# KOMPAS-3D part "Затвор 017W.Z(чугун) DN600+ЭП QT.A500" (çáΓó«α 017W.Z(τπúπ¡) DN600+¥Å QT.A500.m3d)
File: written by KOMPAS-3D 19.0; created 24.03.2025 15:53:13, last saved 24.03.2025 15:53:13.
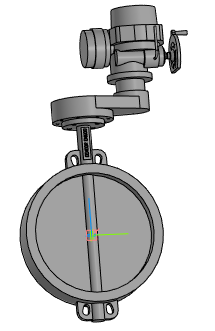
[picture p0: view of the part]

Document properties: Полное имя файла: Затвор 017W.Z(чугун) DN600+ЭП QT.A500.a3d

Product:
- Part/product: Затвор 017W.Z(чугун) DN600+ЭП QT.A500
    Масса: 430.487

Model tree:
1. Операция без истории:1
